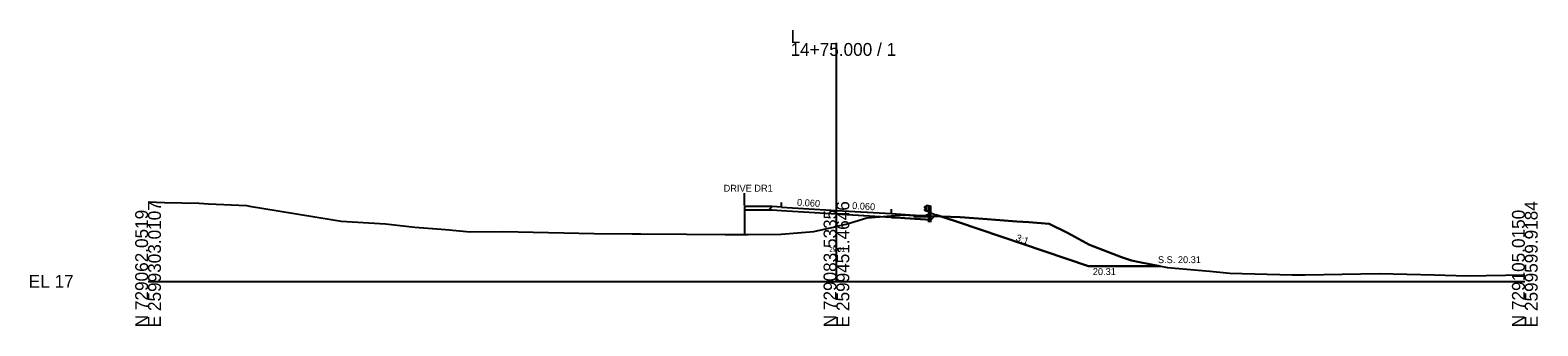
# Model space of a CAD drawing. Extents: x -26 to 3303, y -10 to 9555.
# Drawn here: x -25.7 to 302.8, y 9490.3 to 9554.8 of the extents above; entities that cross this region are included whole.
import ezdxf

# ---------------------------------------------------------------- set-up
doc = ezdxf.new("R2010")
doc.units = 0
for name, color, linetype in [('Exist Cross Section Cell', 7, 'Continuous'), ('Exist XS Center Line Elevation Label', 7, 'Continuous'), ('Exist XS Ground Line', 7, 'Continuous'), ('Prop XS Ditch Slope Text', 7, 'Continuous'), ('Prop XS Ditch Standard Text', 7, 'Continuous'), ('Prop XS Dump Level', 7, 'Continuous'), ('Prop XS Earthwork Shape', 7, 'Continuous'), ('Prop XS EOT Tick Mark', 7, 'Continuous'), ('Prop XS Finish Grade', 7, 'Continuous'), ('Prop XS Finish Grade Earthwork', 7, 'Continuous'), ('Prop XS Finish Grade Paved Shoulder', 7, 'Continuous'), ('Prop XS Finish Grade Pavement', 7, 'Continuous'), ('Prop XS Pvmt Edge Slope', 7, 'Continuous'), ('Prop XS SE Text', 7, 'Continuous'), ('Prop XS SS Elevation Text', 7, 'Continuous'), ('Prop XS Subgrade Earthwork', 7, 'Continuous'), ('Typical Curb CELL', 7, 'Continuous'), ('Typical Guardrail CELL', 7, 'Continuous')]:
    doc.layers.add(name, color=color, linetype=linetype)

msp = doc.modelspace()

# ---------------------------------------------------------------- linework, layer by layer
at = {"layer": 'Exist Cross Section Cell'}
for p, q in [((150, 9500), (150, 9551.97)), ((0, 9500), (150, 9500)), ((150, 9500), (300, 9500))]:
    msp.add_line(p, q, dxfattribs=at)
at = {"layer": 'Exist XS Ground Line'}
msp.add_lwpolyline([(0, 9517.32), (3.61, 9517.23), (11.11, 9517.03), (13.2, 9516.9), (21.44, 9516.53), (22.09, 9516.42), (28.33, 9515.39), (40.3, 9513.42), (42.06, 9513.13), (51.75, 9512.53), (58.15, 9511.81), (64.83, 9511.3), (70.22, 9510.84), (77.34, 9510.9), (97.22, 9510.42), (105.5, 9510.34), (107.37, 9510.35), (117.32, 9510.28), (125.73, 9510.25), (130.74, 9510.22), (137.96, 9510.31), (145.11, 9510.85), (146.69, 9511.22), (149.33, 9511.85), (150, 9512.01), (152.09, 9512.51), (156.63, 9513.87), (163.68, 9514.44), (164.37, 9514.49), (167.12, 9514.39), (176.97, 9513.99), (181.89, 9513.62), (189.34, 9513.08), (191.89, 9512.91), (196.32, 9512.56), (200.33, 9510.62), (205.12, 9508), (212.12, 9505.31), (214.27, 9504.52), (216.06, 9504.16), (222.13, 9503.01), (231.33, 9502.25), (235.75, 9501.82), (249.29, 9501.41), (252.12, 9501.42), (268.23, 9501.73), (280.35, 9501.46), (287.35, 9501.2), (300, 9501.43)], dxfattribs=at)
at = {"layer": 'Prop XS Dump Level'}
for p, q in [((130, 9516.58), (130, 9519.22)), ((138, 9516.21), (150, 9515.49)), ((150, 9515.49), (162, 9514.77))]:
    msp.add_line(p, q, dxfattribs=at)
at = {"layer": 'Prop XS Earthwork Shape'}
for points in [[(135.21, 9515.54), (130, 9515.54), (130, 9510.23), (130.74, 9510.22), (137.96, 9510.31), (145.11, 9510.85), (146.69, 9511.22), (149.33, 9511.85), (150, 9512.01), (152.09, 9512.51), (156.63, 9513.87), (159.37, 9514.09), (150, 9514.66), (138, 9515.38), (136, 9515.5)], [(150, 9512.01), (152.09, 9512.51), (156.63, 9513.87), (159.37, 9514.09), (150, 9514.66), (138, 9515.38), (136, 9515.5), (135.21, 9515.54), (130, 9515.54), (130, 9510.23), (130.74, 9510.22), (137.96, 9510.31), (145.11, 9510.85), (146.69, 9511.22), (149.33, 9511.85)], [(159.37, 9514.09), (163.68, 9514.44), (164.37, 9514.49), (167.12, 9514.39), (171.36, 9514.22), (170.56, 9513.42), (164.89, 9513.76), (164, 9513.82), (162, 9513.94)], [(167.12, 9514.39), (171.36, 9514.22), (170.56, 9513.42), (164.89, 9513.76), (164, 9513.82), (162, 9513.94), (159.37, 9514.09), (163.68, 9514.44), (164.37, 9514.49)], [(171.68, 9514.53), (172.8, 9514.16), (171.36, 9514.22)], [(171.36, 9514.22), (172.8, 9514.16), (171.68, 9514.53)], [(189.34, 9513.08), (191.89, 9512.91), (196.32, 9512.56), (200.33, 9510.62), (205.12, 9508), (212.12, 9505.31), (214.27, 9504.52), (216.06, 9504.16), (220.53, 9503.31), (204.93, 9503.31), (176.4, 9512.96), (172.8, 9514.16), (176.97, 9513.99), (181.89, 9513.62)], [(172.8, 9514.16), (176.4, 9512.96), (204.93, 9503.31), (220.53, 9503.31), (216.06, 9504.16), (214.27, 9504.52), (212.12, 9505.31), (205.12, 9508), (200.33, 9510.62), (196.32, 9512.56), (191.89, 9512.91), (189.34, 9513.08), (181.89, 9513.62), (176.97, 9513.99)]]:
    msp.add_lwpolyline(points, close=True, dxfattribs=at)
at = {"layer": 'Prop XS EOT Tick Mark'}
for p, q in [((138, 9516.21), (138, 9517.21)), ((162, 9514.77), (162, 9515.77))]:
    msp.add_line(p, q, dxfattribs=at)
at = {"layer": 'Prop XS Finish Grade'}
for p, q in [((170.03, 9514.65), (170.56, 9514.91)), ((170.56, 9514.91), (171.68, 9514.53))]:
    msp.add_line(p, q, dxfattribs=at)
at = {"layer": 'Prop XS Finish Grade Earthwork'}
for p, q in [((130, 9515.54), (130, 9510.23)), ((171.68, 9514.53), (176.4, 9512.96)), ((176.4, 9512.96), (204.93, 9503.31)), ((220.53, 9503.31), (204.93, 9503.31))]:
    msp.add_line(p, q, dxfattribs=at)
at = {"layer": 'Prop XS Finish Grade Paved Shoulder'}
for p, q in [((136, 9516.33), (130, 9516.33)), ((130, 9516.33), (130, 9515.54)), ((138, 9516.21), (136, 9516.33)), ((162, 9514.77), (167, 9514.47))]:
    msp.add_line(p, q, dxfattribs=at)
at = {"layer": 'Prop XS Finish Grade Pavement'}
for p, q in [((138, 9516.21), (150, 9515.49)), ((150, 9515.49), (162, 9514.77))]:
    msp.add_line(p, q, dxfattribs=at)
at = {"layer": 'Prop XS Pvmt Edge Slope'}
for p, q in [((136, 9516.33), (135.21, 9515.54)), ((170.56, 9513.42), (171.68, 9514.53)), ((170.01, 9513.98), (170.56, 9513.42))]:
    msp.add_line(p, q, dxfattribs=at)
at = {"layer": 'Prop XS Subgrade Earthwork'}
for p, q in [((135.21, 9515.54), (130, 9515.54)), ((136, 9515.5), (135.21, 9515.54)), ((138, 9515.38), (136, 9515.5)), ((150, 9514.66), (138, 9515.38)), ((162, 9513.94), (150, 9514.66)), ((170.56, 9513.42), (171.68, 9514.53)), ((162, 9513.94), (164, 9513.82)), ((164, 9513.82), (164.89, 9513.76)), ((164.89, 9513.76), (170.56, 9513.42))]:
    msp.add_line(p, q, dxfattribs=at)
at = {"layer": 'Typical Curb CELL'}
for p, q in [((166.99, 9514.05), (167, 9514.46)), ((167, 9514.47), (167, 9514.47)), ((167.01, 9514.47), (169.33, 9514.33)), ((167.23, 9514.2), (167.32, 9514.32)), ((167.32, 9514.32), (167.35, 9514.2)), ((169.33, 9514.33), (170.03, 9514.65)), ((169.83, 9514.33), (169.84, 9514.23)), ((169.98, 9514.28), (169.83, 9514.33)), ((170.01, 9513.98), (170.03, 9514.65)), ((170.01, 9513.98), (166.99, 9514.05)), ((167.35, 9514.2), (167.23, 9514.2)), ((167.99, 9514.13), (168.06, 9514.24)), ((168.16, 9514.16), (167.99, 9514.13)), ((168.06, 9514.24), (168.16, 9514.16)), ((168.48, 9514.17), (168.57, 9514.28)), ((168.6, 9514.17), (168.48, 9514.17)), ((168.57, 9514.28), (168.6, 9514.17)), ((169.24, 9514.1), (169.31, 9514.21)), ((169.41, 9514.13), (169.24, 9514.1)), ((169.31, 9514.21), (169.41, 9514.13)), ((169.84, 9514.23), (169.98, 9514.28))]:
    msp.add_line(p, q, dxfattribs=at)
for centre in [(167.13, 9514.41), (167.49, 9514.33), (169.95, 9514.36), (167.09, 9514.29), (167.55, 9514.15), (167.6, 9514.11), (167.64, 9514.24), (167.71, 9514.24), (167.76, 9514.27), (167.81, 9514.15), (168, 9514.18), (168.21, 9514.16), (168.23, 9514.21), (168.24, 9514.27), (168.29, 9514.13), (168.39, 9514.17), (168.48, 9514.18), (168.6, 9514.12), (168.8, 9514.12), (168.85, 9514.08), (168.89, 9514.21), (169.01, 9514.23), (169.06, 9514.12), (169.25, 9514.15), (169.28, 9514.05), (169.46, 9514.13), (169.48, 9514.18), (169.73, 9514.15), (169.85, 9514.09)]:
    msp.add_circle(centre, 0.00802, dxfattribs=at)
msp.add_arc((167.01, 9514.46), 0.0104, 86.5213, 178.5693, dxfattribs=at)
at = {"layer": 'Typical Guardrail CELL'}
for p, q in [((169.53, 9516.44), (169.24, 9516.23)), ((169.53, 9515.9), (169.24, 9516.1)), ((169.53, 9515.81), (169.24, 9515.61)), ((169.53, 9515.28), (169.24, 9515.48)), ((170.03, 9516.44), (169.53, 9516.44)), ((169.53, 9516.44), (169.53, 9515.28)), ((169.53, 9515.86), (169.53, 9515.9)), ((169.53, 9515.86), (169.53, 9515.81)), ((170.03, 9515.28), (169.53, 9515.28)), ((170.03, 9516.44), (170.03, 9513.95)), ((170.03, 9516.44), (170.53, 9516.44)), ((170.53, 9516.44), (170.53, 9513.95)), ((170.03, 9513.95), (170.53, 9513.95)), ((170.03, 9513.95), (170.03, 9512.94)), ((170.53, 9513.95), (170.53, 9512.94))]:
    msp.add_line(p, q, dxfattribs=at)
for centre, start, end in [((169.29, 9516.17), 125.003, 235.0112), ((169.29, 9515.54), 125.0059, 235.0366)]:
    msp.add_arc(centre, 0.0776, start, end, dxfattribs=at)

# ---------------------------------------------------------------- texts
at = {"layer": 'Exist Cross Section Cell'}
for s, p in [('L', (140, 9551.97)), ('14+75.000 / 1', (140, 9549.17)), ('EL 17', (-26, 9498.6))]:
    msp.add_text(s, height=2.8, dxfattribs=at).set_placement(p)
for s, p in [('N 729062.0519', (0, 9490)), ('E 2599303.0107', (2.8, 9490)), ('N 729083.5335', (150, 9490)), ('E 2599451.4646', (152.8, 9490)), ('N 729105.0150', (300, 9490)), ('E 2599599.9184', (302.8, 9490))]:
    msp.add_text(s, height=2.8, rotation=90, dxfattribs=at).set_placement(p)
at = {"layer": 'Exist XS Center Line Elevation Label'}
msp.add_text('29.01', height=1, dxfattribs=at).set_placement((148.43, 9506.51))
at = {"layer": 'Prop XS Ditch Slope Text'}
msp.add_text('3:1', height=1.5, rotation=340.5558, dxfattribs=at).set_placement((188.97, 9508.92))
at = {"layer": 'Prop XS Ditch Standard Text'}
msp.add_text('20.31', height=1.5, dxfattribs=at).set_placement((205.87, 9501.39))
at = {"layer": 'Prop XS Dump Level'}
for s, height, p in [('Eop', 0.3, (164.37, 9514.19)), ('Eop', 0.3, (164.37, 9514.19)), ('Case1', 0.04, (170, 9514.13)), ('Case1', 0.04, (173, 9513.89))]:
    msp.add_text(s, height=height, dxfattribs=at).set_placement(p)
at = {"layer": 'Prop XS SE Text'}
for s, rotation, p in [('DRIVE DR1', 0.0906, (125.42, 9519.56)), ('0.060', 356.5664, (141.38, 9516.51)), ('0.060', 356.5664, (153.38, 9515.79))]:
    msp.add_text(s, height=1.5, rotation=rotation, dxfattribs=at).set_placement(p)
at = {"layer": 'Prop XS SS Elevation Text'}
msp.add_text('S.S. 20.31', height=1.5, dxfattribs=at).set_placement((220.06, 9503.98))

doc.saveas('drawing.dxf')
